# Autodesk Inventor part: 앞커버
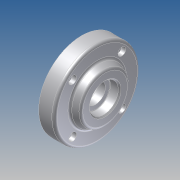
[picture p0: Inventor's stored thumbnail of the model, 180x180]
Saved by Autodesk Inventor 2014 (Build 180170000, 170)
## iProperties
Company: 한국ATC센터
Created: 2014-02
Part Number: 앞커버
Document SubType Name: Modeling
Designer: KYOUNG IL JANG
Density: 2.71 g/cm^3
Mass: 114.339 g
Surface Area: 117.889 cm^2
Volume: 42.1916 cm^3
Material: 알루미늄-6061
Vendor: CBT Solutions
Appearance: 알루미늄 - 평지
Author: KYOUNG IL JANG
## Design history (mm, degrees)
sketch "스케치1"
  geometry: L1 (-11.5, 0)-(11.5, 0); L2 (11.5, 0)-(11.5, 22.5); L3 (11.5, 22.5)-(6.5, 22.5); L4 (6.5, 22.5)-(6.5, 32.5); L5 (6.5, 32.5)-(-5.5, 32.5); L6 (-5.5, 32.5)-(-5.5, 21); L7 (-5.5, 21)-(-11.5, 18.202); L8 (-11.5, 18.202)-(-11.5, 0); 2 further points
  constraints: 16 end point, 3 parallel, 3 perpendicular, 1 coincident, 1 horizontal, 1 midpoint
  dimensions: "d0" = 23 distance of L1.start L1.end; "d1" = 65 diameter of L5 L1; "d2" = 45 diameter of L3 L1; "d3" = 42 diameter of L6.end L1; "d4" = 115 deg angle of L7 L6; "d5" = 12 distance of L4.end L5.end; "d6" = 5 distance of L2.end L3.end
revolve "회전1" sketch "스케치1" stored, may be unused: angle "d7" = 90 deg
sketch "스케치2"
  geometry: L1 (0, 0)-(32.5, 0); L2 (0, 0)-(18.738, 18.738); 1 further point
  constraints: 4 end point, 1 horizontal, 1 horizontal alignment, 1 other
  dimensions: "d8" = 45 deg angle of L1 L2; "d9" = 26.5 distance of L1.start L2.end
hole "구멍1" sketch "스케치2" at (18.738, 18.738) diameter "d10" = 3.4; stored, may be unused: countersink angle "d14" = 90 deg, drill point angle "d16" = 118 deg; dims "d11" = 6, "d12" = 6, "d13" = 3.3, "d15" = 8
fillet "모깎기1" dims "d20" = 2
hole "구멍2" diameter "d23" = 15; stored, may be unused: countersink angle "d27" = 90 deg, drill point angle "d29" = 118 deg; dims "d21" = 10, "d22" = 10, "d24" = 6, "d25" = 32, "d26" = 10, "d28" = 8
hole "구멍3" diameter "d32" = 22; stored, may be unused: countersink angle "d36" = 90 deg, drill point angle "d38" = 0 deg; dims "d30" = 10, "d31" = 10, "d33" = 6, "d34" = 32, "d35" = 10, "d37" = 7.3
chamfer "모따기1" distance "d39" = 1; stored, may be unused: second distance "d40" = 2, angle "d41" = 45 deg
fillet "모깎기2" dims "d42" = 0.3
node "솔리드1"
pattern_circular "원형 패턴1" dims angle "d18" = 360 deg
